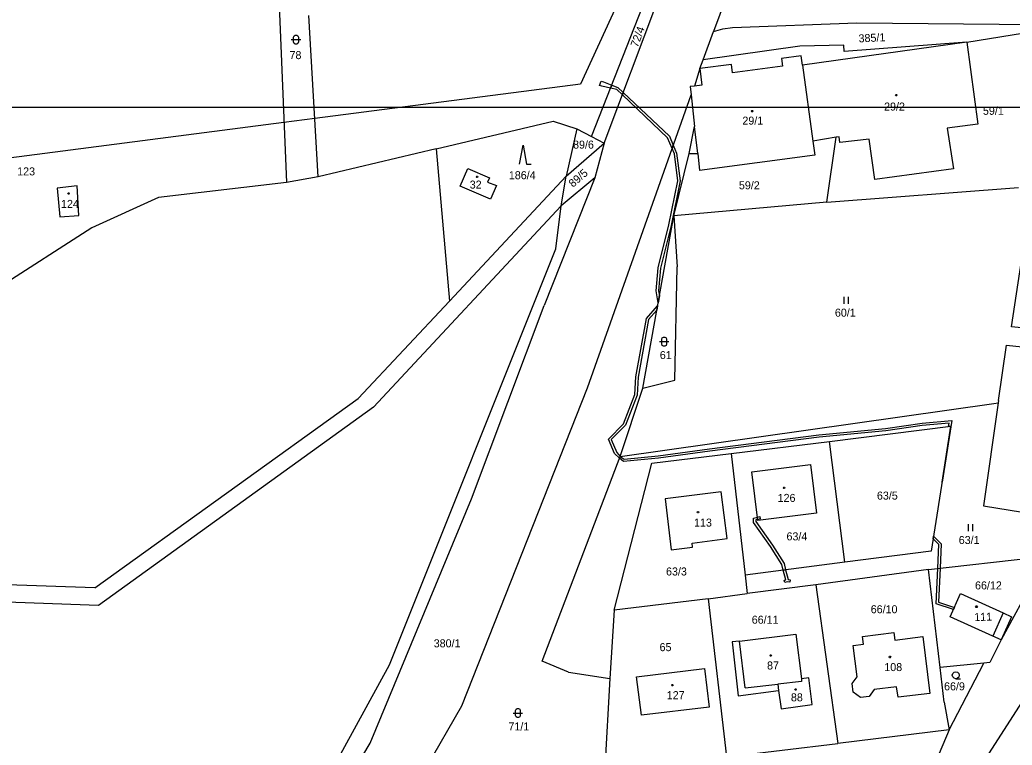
# Model space of a CAD drawing. Extents: x -811039 to -805820, y -1161436 to -1155864.
# Drawn here: x -806771.7 to -806560.9, y -1158135.5 to -1157981.5 of the extents above; entities that cross this region are included whole.
import ezdxf

# ---------------------------------------------------------------- set-up
doc = ezdxf.new("R2010")
doc.units = 0
for name, color, linetype in [('Default', 7, 'Continuous'), ('Hranice parcel', 7, 'Continuous'), ('ML1000', 7, 'Continuous'), ('Parcelní čísla', 7, 'Continuous'), ('Vnitřní kresba', 7, 'Continuous'), ('Věcná břemena k části', 7, 'Continuous'), ('Značky budov', 7, 'Continuous'), ('Značky kultur', 7, 'Continuous')]:
    doc.layers.add(name, color=color, linetype=linetype)

# ---------------------------------------------------------------- blocks, each defined once
blk = doc.blocks.new('304')
at = {"layer": 'Default'}
blk.add_lwpolyline([(0, 0), (-0.38, 0.1), (-0.65, 0.37), (-0.75, 0.74), (-0.65, 1.11), (-0.38, 1.38), (-0.01, 1.48), (0.36, 1.38), (0.63, 1.11), (0.73, 0.73), (0.63, 0.35), (0.36, 0.08), (-0.02, -0.02), (0.98, -0.02)], dxfattribs=at)
blk = doc.blocks.new('306')
at = {"layer": 'Default'}
for p, q in [((-0.5, 1.5), (-0.5, 0)), ((0.5, 0), (0.5, 1.5))]:
    blk.add_line(p, q, dxfattribs=at)
blk = doc.blocks.new('308')
at = {"layer": 'Default'}
blk.add_lwpolyline([(-0.75, 0), (0, 4), (0.75, 0), (1.75, 0)], dxfattribs=at)
blk = doc.blocks.new('316')
at = {"layer": 'Default'}
for points in [[(-1, 1), (0.27, 1), (1, 1)], [(-0.5, 1.5), (-0.4, 1.79), (-0.15, 1.97), (0.16, 1.97), (0.41, 1.79), (0.51, 1.5), (0.51, 0.5), (0.41, 0.21), (0.16, 0.03), (-0.15, 0.03), (-0.4, 0.21), (-0.5, 0.5), (-0.5, 1.5)]]:
    blk.add_lwpolyline(points, dxfattribs=at)
blk = doc.blocks.new('402')
at = {"layer": 'Default'}
blk.add_lwpolyline([(0.09, 0.15), (0.18, 0), (0.09, -0.15), (-0.09, -0.15), (-0.18, 0), (-0.09, 0.15), (0.09, 0.15)], dxfattribs=at)

msp = doc.modelspace()

# ---------------------------------------------------------------- linework, layer by layer
at = {"layer": 'Hranice parcel'}
for p, q in [((-806650.25, -1158006.25), (-806630.4, -1157955.86)), ((-806618.72, -1157968.82), (-806624.34, -1157983.98)), ((-806716.77, -1157975.04), (-806715.04, -1158016)), ((-806647.57, -1158007.68), (-806636.14, -1157977.4)), ((-806708.29, -1158014.83), (-806710.29, -1157980.53)), ((-806622.35, -1157983.37), (-806620.27, -1157983.09)), ((-806620.27, -1157983.09), (-806593.91, -1157982.13)), ((-806593.91, -1157982.13), (-806547.55, -1157982.51)), ((-806570.5, -1157986.22), (-806547.55, -1157982.51)), ((-806626.56, -1157989.99), (-806624.34, -1157983.98)), ((-806624.34, -1157983.98), (-806622.35, -1157983.37)), ((-806605.97, -1157987.04), (-806626.56, -1157989.99)), ((-806596.64, -1157986.83), (-806605.97, -1157987.04)), ((-806570.5, -1157986.22), (-806605.46, -1157991.06)), ((-806596.57, -1157988.21), (-806596.64, -1157986.83)), ((-806570.5, -1157986.22), (-806596.57, -1157988.21)), ((-806570.5, -1157986.22), (-806568.17, -1158003.62)), ((-806627.24, -1157991.82), (-806626.56, -1157989.99)), ((-806605.46, -1157991.06), (-806603.27, -1158007.25)), ((-806627.24, -1157991.82), (-806628.4, -1157995.55)), ((-806628.4, -1157995.55), (-806629.31, -1157995.65)), ((-806629.31, -1157995.65), (-806629.11, -1157997.36)), ((-806651.08, -1158059.61), (-806629.11, -1157997.36)), ((-806629.11, -1157997.36), (-806628.34, -1158004.14)), ((-806683.24, -1158008.88), (-806658.37, -1158003)), ((-806658.37, -1158003), (-806653.36, -1158004.59)), ((-806629.49, -1158009.85), (-806628.34, -1158004.14)), ((-806568.17, -1158003.62), (-806574.68, -1158004.5)), ((-806653.36, -1158004.59), (-806655.66, -1158014.66)), ((-806653.36, -1158004.59), (-806650.25, -1158006.25)), ((-806650.25, -1158006.25), (-806647.57, -1158007.68)), ((-806598.29, -1158006.41), (-806603.27, -1158007.25)), ((-806600.28, -1158020.19), (-806598.29, -1158006.41)), ((-806597.67, -1158006.3), (-806598.29, -1158006.41)), ((-806597.53, -1158007.53), (-806597.67, -1158006.3)), ((-806574.68, -1158004.5), (-806573.37, -1158013.12)), ((-806655.66, -1158014.66), (-806647.57, -1158007.68)), ((-806647.57, -1158007.68), (-806649.57, -1158015.03)), ((-806603.27, -1158007.25), (-806602.78, -1158010.18)), ((-806591.24, -1158006.79), (-806597.53, -1158007.53)), ((-806590.06, -1158015.35), (-806591.24, -1158006.79)), ((-806683.24, -1158008.88), (-806708.29, -1158014.83)), ((-806683.24, -1158008.88), (-806680.42, -1158041.23)), ((-806632.78, -1158023.07), (-806629.49, -1158009.85)), ((-806629.49, -1158009.85), (-806627.69, -1158009.82)), ((-806627.69, -1158009.82), (-806627.28, -1158013.43)), ((-806602.78, -1158010.18), (-806627.28, -1158013.43)), ((-806708.29, -1158014.83), (-806715.04, -1158016)), ((-806655.66, -1158014.66), (-806680.42, -1158041.23)), ((-806678.15, -1158016.79), (-806676.53, -1158013.05)), ((-806676.53, -1158013.05), (-806671.94, -1158015.04)), ((-806656.73, -1158020.99), (-806655.66, -1158014.66)), ((-806573.37, -1158013.12), (-806590.06, -1158015.35)), ((-806759.54, -1158016.7), (-806763.74, -1158017.18)), ((-806759.18, -1158023), (-806759.54, -1158016.7)), ((-806715.04, -1158016), (-806742.23, -1158019.17)), ((-806671.73, -1158019.53), (-806678.15, -1158016.79)), ((-806671.94, -1158015.04), (-806672.35, -1158015.95)), ((-806672.35, -1158015.95), (-806670.44, -1158016.66)), ((-806670.44, -1158016.66), (-806671.73, -1158019.53)), ((-806649.57, -1158015.03), (-806660.29, -1158042.1)), ((-806649.57, -1158015.03), (-806656.73, -1158020.99)), ((-806763.74, -1158017.18), (-806763.22, -1158023.33)), ((-806600.28, -1158020.19), (-806559.56, -1158017.1)), ((-806742.23, -1158019.17), (-806756.36, -1158025.64)), ((-806696.59, -1158063.72), (-806656.73, -1158020.99)), ((-806657.82, -1158030.08), (-806656.73, -1158020.99)), ((-806600.28, -1158020.19), (-806632.78, -1158023.07)), ((-806561.02, -1158046.66), (-806556.99, -1158020.02)), ((-806763.22, -1158023.33), (-806759.18, -1158023)), ((-806639.36, -1158059.7), (-806632.78, -1158023.07)), ((-806632.78, -1158023.07), (-806632.07, -1158033.91)), ((-806756.36, -1158025.64), (-806779.2, -1158040.26)), ((-806693.13, -1158118.44), (-806657.82, -1158030.08)), ((-806632.57, -1158057.99), (-806632.07, -1158033.91)), ((-806699.85, -1158061.84), (-806680.42, -1158041.23)), ((-806675.76, -1158083.19), (-806660.29, -1158042.1)), ((-806535.38, -1158049.27), (-806561.02, -1158046.66)), ((-806563.8, -1158062.27), (-806562.08, -1158050.54)), ((-806562.08, -1158050.54), (-806536.5, -1158053.32)), ((-806639.36, -1158059.7), (-806632.57, -1158057.99)), ((-806677.82, -1158127.15), (-806651.08, -1158059.61)), ((-806644.16, -1158074.21), (-806639.36, -1158059.7)), ((-806755.75, -1158102.03), (-806699.85, -1158061.84)), ((-806644.16, -1158074.21), (-806564.76, -1158062.95)), ((-806563.88, -1158062.82), (-806566.96, -1158084.66)), ((-806564.76, -1158062.95), (-806563.88, -1158062.82)), ((-806563.8, -1158062.27), (-806563.88, -1158062.82)), ((-806696.59, -1158063.72), (-806754.99, -1158105.78)), ((-806599.72, -1158070.98), (-806573.94, -1158067.75)), ((-806573.94, -1158067.75), (-806578.11, -1158094.28)), ((-806620.58, -1158073.54), (-806599.72, -1158070.98)), ((-806596.44, -1158096.58), (-806599.72, -1158070.98)), ((-806637.41, -1158075.58), (-806620.58, -1158073.54)), ((-806620.58, -1158073.54), (-806617.63, -1158099.35)), ((-806660.71, -1158117.63), (-806644.16, -1158074.21)), ((-806645.47, -1158106.82), (-806637.41, -1158075.58)), ((-806616.21, -1158077.45), (-806603.76, -1158075.89)), ((-806603.76, -1158075.89), (-806602.48, -1158086.22)), ((-806614.92, -1158087.77), (-806616.21, -1158077.45)), ((-806622.68, -1158081.65), (-806634.58, -1158083.17)), ((-806621.43, -1158091.62), (-806622.68, -1158081.65)), ((-806697.27, -1158135.03), (-806675.76, -1158083.19)), ((-806634.58, -1158083.17), (-806633.31, -1158094)), ((-806602.48, -1158086.22), (-806614.92, -1158087.77)), ((-806566.96, -1158084.66), (-806551.02, -1158087.22)), ((-806628.88, -1158092.55), (-806621.43, -1158091.62)), ((-806628.77, -1158093.44), (-806628.88, -1158092.55)), ((-806633.31, -1158094), (-806628.77, -1158093.44)), ((-806578.11, -1158094.28), (-806596.44, -1158096.58)), ((-806596.44, -1158096.58), (-806617.63, -1158099.35)), ((-806578.67, -1158098.14), (-806553.63, -1158095.33)), ((-806553.63, -1158095.33), (-806563.21, -1158113.11)), ((-806578.67, -1158098.14), (-806602.6, -1158101.43)), ((-806576.22, -1158118.97), (-806578.67, -1158098.14)), ((-806755.75, -1158102.03), (-806826.2, -1158099.73)), ((-806617.63, -1158099.35), (-806617.15, -1158103.27)), ((-806754.99, -1158105.78), (-806823.76, -1158103.31)), ((-806625.5, -1158104.42), (-806617.15, -1158103.27)), ((-806602.6, -1158101.43), (-806617.15, -1158103.27)), ((-806602.6, -1158101.43), (-806597.92, -1158135.1)), ((-806574.04, -1158108.24), (-806571.85, -1158103.3)), ((-806571.85, -1158103.3), (-806562.79, -1158107.37)), ((-806625.5, -1158104.42), (-806645.47, -1158106.82)), ((-806625.5, -1158104.42), (-806621.6, -1158137.92)), ((-806645.47, -1158106.82), (-806646.33, -1158121.28)), ((-806562.79, -1158107.37), (-806561.02, -1158108.21)), ((-806564.99, -1158112.33), (-806574.04, -1158108.24)), ((-806561.02, -1158108.21), (-806563.21, -1158113.11)), ((-806592.69, -1158112.36), (-806586, -1158111.55)), ((-806586, -1158111.55), (-806585.79, -1158113.16)), ((-806618.83, -1158113.37), (-806620.39, -1158113.54)), ((-806620.39, -1158113.54), (-806619.09, -1158125.02)), ((-806618.83, -1158113.37), (-806606.85, -1158111.91)), ((-806606.85, -1158111.91), (-806605.66, -1158121.36)), ((-806592.49, -1158114), (-806592.69, -1158112.36)), ((-806585.79, -1158113.16), (-806579.88, -1158112.41)), ((-806579.88, -1158112.41), (-806578.35, -1158124.49)), ((-806563.21, -1158113.11), (-806565.64, -1158117.94)), ((-806563.21, -1158113.11), (-806564.99, -1158112.33)), ((-806594.69, -1158114.28), (-806592.49, -1158114)), ((-806593.85, -1158120.96), (-806594.69, -1158114.28)), ((-806655.15, -1158119.99), (-806660.71, -1158117.63)), ((-806566.94, -1158118.07), (-806576.22, -1158118.97)), ((-806574.25, -1158132.24), (-806566.94, -1158118.07)), ((-806565.64, -1158117.94), (-806566.94, -1158118.07)), ((-806723.74, -1158174.06), (-806693.13, -1158118.44)), ((-806655.15, -1158119.99), (-806646.33, -1158121.28)), ((-806640.69, -1158120.97), (-806626.23, -1158119.19)), ((-806626.23, -1158119.19), (-806625.27, -1158127.43)), ((-806575.35, -1158126.31), (-806576.22, -1158118.97)), ((-806646.33, -1158121.28), (-806647.48, -1158140.75)), ((-806639.65, -1158129.1), (-806640.69, -1158120.97)), ((-806605.64, -1158121.92), (-806610.66, -1158122.49)), ((-806604.07, -1158121.2), (-806605.66, -1158121.36)), ((-806605.66, -1158121.36), (-806605.64, -1158121.92)), ((-806603.4, -1158126.84), (-806604.07, -1158121.2)), ((-806594.87, -1158122.36), (-806593.85, -1158120.96)), ((-806594.66, -1158124.22), (-806594.87, -1158122.36)), ((-806619.09, -1158125.02), (-806610.53, -1158123.85)), ((-806610.66, -1158122.49), (-806610.53, -1158123.85)), ((-806610.53, -1158123.85), (-806609.99, -1158127.72)), ((-806593.12, -1158125.33), (-806594.66, -1158124.22)), ((-806590.21, -1158123.68), (-806591.24, -1158125.1)), ((-806585.43, -1158123.05), (-806590.21, -1158123.68)), ((-806585.1, -1158125.31), (-806585.43, -1158123.05)), ((-806578.35, -1158124.49), (-806585.1, -1158125.31)), ((-806591.24, -1158125.1), (-806593.12, -1158125.33)), ((-806575.35, -1158126.31), (-806574.25, -1158132.24)), ((-806558.78, -1158126.18), (-806568.02, -1158140.53)), ((-806718.26, -1158196.99), (-806677.82, -1158127.15)), ((-806625.27, -1158127.43), (-806639.65, -1158129.1)), ((-806609.99, -1158127.72), (-806603.4, -1158126.84)), ((-806574.25, -1158132.24), (-806597.92, -1158135.1)), ((-806574.25, -1158132.24), (-806577.2, -1158139.11)), ((-806721.04, -1158174.85), (-806697.27, -1158135.03)), ((-806621.6, -1158137.92), (-806597.92, -1158135.1))]:
    msp.add_line(p, q, dxfattribs=at)
at = {"layer": 'ML1000'}
msp.add_lwpolyline([(-806875, -1157000), (-806875, -1158000), (-806250, -1158000), (-806250, -1157000)], close=True, dxfattribs=at)
at = {"layer": 'Vnitřní kresba'}
for p, q in [((-806605.73, -1157989.14), (-806609.88, -1157989.69)), ((-806605.46, -1157991.06), (-806605.73, -1157989.14)), ((-806620.5, -1157990.95), (-806627.24, -1157991.82)), ((-806620.28, -1157992.72), (-806620.5, -1157990.95)), ((-806609.66, -1157991.3), (-806620.28, -1157992.72)), ((-806609.88, -1157989.69), (-806609.66, -1157991.3)), ((-806627.24, -1157991.82), (-806626.81, -1157995.37)), ((-806626.81, -1157995.37), (-806628.4, -1157995.55)), ((-806627.69, -1158009.82), (-806628.34, -1158004.14)), ((-806562.79, -1158107.37), (-806564.99, -1158112.33)), ((-806617.6, -1158123.27), (-806618.83, -1158113.37)), ((-806617.6, -1158123.27), (-806610.66, -1158122.49))]:
    msp.add_line(p, q, dxfattribs=at)
at = {"layer": 'Věcná břemena k části'}
for points in [[(-806834.98, -1157967.84), (-806789.3, -1157959.45), (-806742.1, -1157950.78), (-806718.6, -1157948.56), (-806718.2, -1157948.52), (-806631.31, -1157940.29), (-806630.87, -1157947.76), (-806652.6, -1157995.12), (-806709.01, -1158002.43), (-806715.58, -1158003.28), (-806828.66, -1158017.95), (-806829.24, -1158014.95), (-806831.65, -1157986.44)], [(-806834.98, -1157967.84), (-806789.3, -1157959.45), (-806742.1, -1157950.78), (-806718.6, -1157948.56), (-806718.2, -1157948.52), (-806631.31, -1157940.29), (-806630.87, -1157947.76), (-806652.6, -1157995.12), (-806709.01, -1158002.43), (-806715.58, -1158003.28), (-806828.66, -1158017.95), (-806829.24, -1158014.95), (-806831.65, -1157986.44)], [(-806646.2, -1157995.97), (-806648.09, -1157995.57), (-806648.55, -1157995.38), (-806648.17, -1157994.46), (-806647.71, -1157994.65), (-806645.94, -1157995.32)], [(-806643.69, -1157997.39), (-806644.89, -1157996.25), (-806646.2, -1157995.97), (-806645.94, -1157995.32), (-806644.63, -1157995.81), (-806643.5, -1157996.89)], [(-806633.15, -1158008.78), (-806634.12, -1158006.49), (-806643.69, -1157997.39), (-806643.5, -1157996.89), (-806633.7, -1158006.19), (-806632.9, -1158008.09)], [(-806632.9, -1158008.09), (-806632.17, -1158009.81), (-806631.43, -1158015.68), (-806633.36, -1158025.1), (-806635.58, -1158034.22), (-806636.01, -1158038.99), (-806635.83, -1158040.06), (-806636.1, -1158041.55), (-806636.51, -1158039.01), (-806636.08, -1158034.14), (-806633.84, -1158025), (-806631.93, -1158015.66), (-806632.65, -1158009.95), (-806633.15, -1158008.78)], [(-806609.51, -1158098.29), (-806609.81, -1158097.13), (-806612.2, -1158093.28), (-806615.84, -1158088.16), (-806615.87, -1158087.24), (-806615.01, -1158087.05), (-806614.51, -1158086.94), (-806614.4, -1158087.42), (-806614.95, -1158087.55), (-806615.35, -1158087.64), (-806615.34, -1158088), (-806611.78, -1158093), (-806609.35, -1158096.93), (-806609.02, -1158098.22)], [(-806577.6, -1158091.06), (-806575.95, -1158092.69), (-806576.19, -1158097.86), (-806576.52, -1158105.13), (-806573.15, -1158106.21), (-806573.35, -1158106.67), (-806577.04, -1158105.49), (-806576.69, -1158097.92), (-806576.45, -1158092.89), (-806577.7, -1158091.67)], [(-806609.02, -1158098.22), (-806608.48, -1158100.31), (-806608.05, -1158100.37), (-806608.12, -1158100.86), (-806608.66, -1158100.79), (-806609.2, -1158100.94), (-806609.34, -1158100.46), (-806608.98, -1158100.36), (-806609.51, -1158098.29)]]:
    msp.add_lwpolyline(points, close=True, dxfattribs=at)
for points in [[(-806644.28, -1158074.53), (-806645.35, -1158073.56), (-806646.62, -1158070.47), (-806643.43, -1158067.25), (-806641.08, -1158061.03), (-806640.86, -1158057.3), (-806638.57, -1158044.87), (-806636.21, -1158042.18), (-806636.39, -1158043.14)], [(-806636.39, -1158043.14), (-806638.11, -1158045.09), (-806640.36, -1158057.36), (-806640.58, -1158061.13), (-806643.01, -1158067.53), (-806646.04, -1158070.59), (-806644.89, -1158073.36), (-806644.16, -1158074.21)], [(-806644.16, -1158074.21), (-806643.29, -1158074.73), (-806636.11, -1158074.02), (-806625.2, -1158072.53), (-806601.98, -1158069.55), (-806587.77, -1158068.2), (-806580.04, -1158067.09), (-806573.69, -1158066.56), (-806575.74, -1158079.65), (-806573.94, -1158067.75), (-806574.4, -1158067.81), (-806574.29, -1158067.12), (-806579.98, -1158067.59), (-806587.71, -1158068.7), (-806601.92, -1158070.05), (-806625.14, -1158073.03), (-806636.05, -1158074.52), (-806643.45, -1158075.25), (-806644.28, -1158074.53)]]:
    msp.add_lwpolyline(points, dxfattribs=at)

# ---------------------------------------------------------------- block references
at = {"layer": 'Značky budov'}
for p in [(-806585.53, -1157997.47), (-806616.12, -1158000.84), (-806674.55, -1158014.79), (-806761.34, -1158018.33), (-806609.33, -1158080.84), (-806627.61, -1158086.02), (-806568.47, -1158106.06), (-806612.17, -1158116.43), (-806586.87, -1158116.75), (-806633.05, -1158122.73), (-806606.91, -1158123.63)]:
    msp.add_blockref('402', p, dxfattribs=at)
at = {"layer": 'Značky kultur'}
for name, p in [('316', (-806713.03, -1157986.67)), ('308', (-806664.8, -1158012.1)), ('306', (-806596.13, -1158041.79)), ('316', (-806634.82, -1158050.79)), ('306', (-806569.76, -1158090.02)), ('304', (-806572.86, -1158121.35)), ('316', (-806665.89, -1158129.64))]:
    msp.add_blockref(name, p, dxfattribs=at)

# ---------------------------------------------------------------- texts
at = {"layer": 'Parcelní čísla'}
for s, rotation, p in [('72/4', 69.5, (-806640.44, -1157987.43)), ('385/1', 2.636, (-806593.48, -1157986.27)), ('89/5', 40.795, (-806654.2, -1158017.14)), ('111', 1.833, (-806568.92, -1158109.13))]:
    msp.add_text(s, height=1.7, rotation=rotation, dxfattribs=at).set_placement(p)
for s, p in [('78', (-806714.4, -1157989.81)), ('29/2', (-806588.1, -1158000.73)), ('59/1', (-806567.1, -1158001.63)), ('29/1', (-806618.2, -1158003.72)), ('89/6', (-806654.17, -1158008.81)), ('123', (-806772.25, -1158014.5)), ('186/4', (-806667.81, -1158015.31)), ('32', (-806676.12, -1158017.3)), ('59/2', (-806618.94, -1158017.45)), ('124', (-806762.94, -1158021.4)), ('60/1', (-806598.55, -1158044.49)), ('61', (-806635.74, -1158053.49)), ('126', (-806610.71, -1158083.82)), ('63/5', (-806589.62, -1158083.33)), ('113', (-806628.47, -1158089.06)), ('63/4', (-806608.83, -1158091.99)), ('63/1', (-806572.24, -1158092.76)), ('63/3', (-806634.42, -1158099.44)), ('66/12', (-806568.78, -1158102.4)), ('66/10', (-806590.94, -1158107.46)), ('66/11', (-806616.21, -1158109.68)), ('380/1', (-806683.77, -1158114.69)), ('65', (-806635.79, -1158115.51)), ('87', (-806612.96, -1158119.4)), ('108', (-806588.05, -1158119.74)), ('66/9', (-806575.36, -1158123.82)), ('127', (-806634.27, -1158125.7)), ('88', (-806607.89, -1158126.16)), ('71/1', (-806667.9, -1158132.34))]:
    msp.add_text(s, height=1.7, dxfattribs=at).set_placement(p)

doc.saveas('drawing.dxf')
